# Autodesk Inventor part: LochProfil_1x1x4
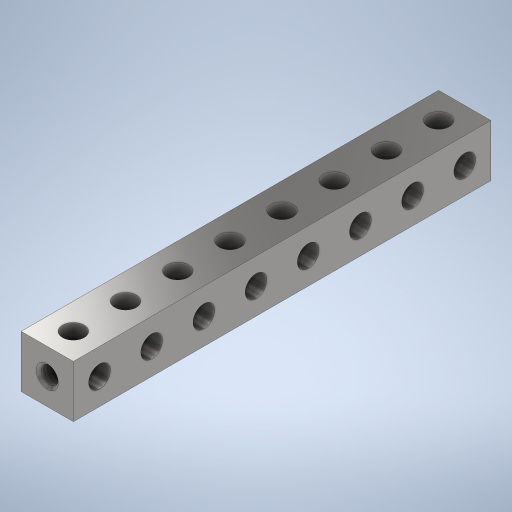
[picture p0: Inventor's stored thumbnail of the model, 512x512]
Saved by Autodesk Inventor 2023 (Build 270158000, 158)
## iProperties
Created: 2023-11
Part Number: LochProfil_1x1x4
Material: Edelstahl
Document SubType Name: Modeling
Designer: Greiner
Density: 8 g/cm^3
Appearance: Halbpoliert
Radius: 2,075 mm
Einheitsmaß: 10,000 mm
Author: Greiner
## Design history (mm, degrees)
sketch "Skizze1"
  geometry: L1 (5, 40)-(-5, 40); L2 (-5, 40)-(-5, -40); L3 (-5, -40)-(5, -40); L4 (5, -40)-(5, 40); 3 further points
  constraints: 8 end point, 2 midpoint, 2 parallel, 1 horizontal, 1 horizontal alignment, 1 perpendicular, 1 vertical alignment
  dimensions: "d0" = 80 distance of L3.end L1.start (computed from Löcher, Einheitsmaß); "d1" = 10 distance of L1.start L1.end (= Einheitsmaß)
extrude "Extrusion1" new body sketch "Skizze1" stored distance "d2" = 10 (= Einheitsmaß); taper "d3" = 0 deg
sketch "Skizze2"
  geometry: C1 r 2.075 at (0, -35); 1 further point
  constraints: 1 centre point, 1 vertical alignment
  dimensions: "d4" = 4.15 diameter of C1 (= 2 x Radius); "d5" = 35 distance of point (0, 0) C1.centre (computed from Löcher, Einheitsmaß)
sketch "Skizze4"
  geometry: C1 r 2.075 at (-75, 5); 1 further point
  constraints: 1 centre point, 1 horizontal alignment
  dimensions: "d6" = 4.15 diameter of C1 (= 2 x Radius); "d7" = 35 distance of point (-40, 5) C1.centre (computed from Löcher, Einheitsmaß)
extrude "Extrusion2" cut sketch "Skizze2" distance "d8" = 10 (= Einheitsmaß); taper "d9" = 0 deg
extrude "Extrusion3" cut sketch "Skizze4" distance "d10" = 10 (= Einheitsmaß); taper "d11" = 0 deg
pattern_linear "Rechteckige Anordnung1" dims "d14" = 10 (= Einheitsmaß)
sketch "Skizze5"
  geometry: 2 further points
  constraints: 1 coincident
hole "Bohrung1" sketch "Skizze5" at (5, -5) diameter "d15" = 3.242; stored, may be unused: countersink angle "d19" = 90 deg, drill point angle "d21" = 118 deg; dims "d16" = 5 (= 0.5 x Einheitsmaß), "d17" = 4, "d18" = 2, "d20" = 10.8 (computed from Einheitsmaß)
mirror "Spiegeln1"
chamfer "Fase2" distance "d25" = 0.5 (= Fasen); stored, may be unused: second distance "d26" = 2, angle "d27" = 45 deg
node "Volumenkörper1"
other parameters: "Einheitsmaß" = 10 [user parameter; used in 10 equation terms], "Radius" = 2.075 [user parameter; used in 2 equation terms], "Fasen" = 0.5 [user parameter; used in 1 equation term]
